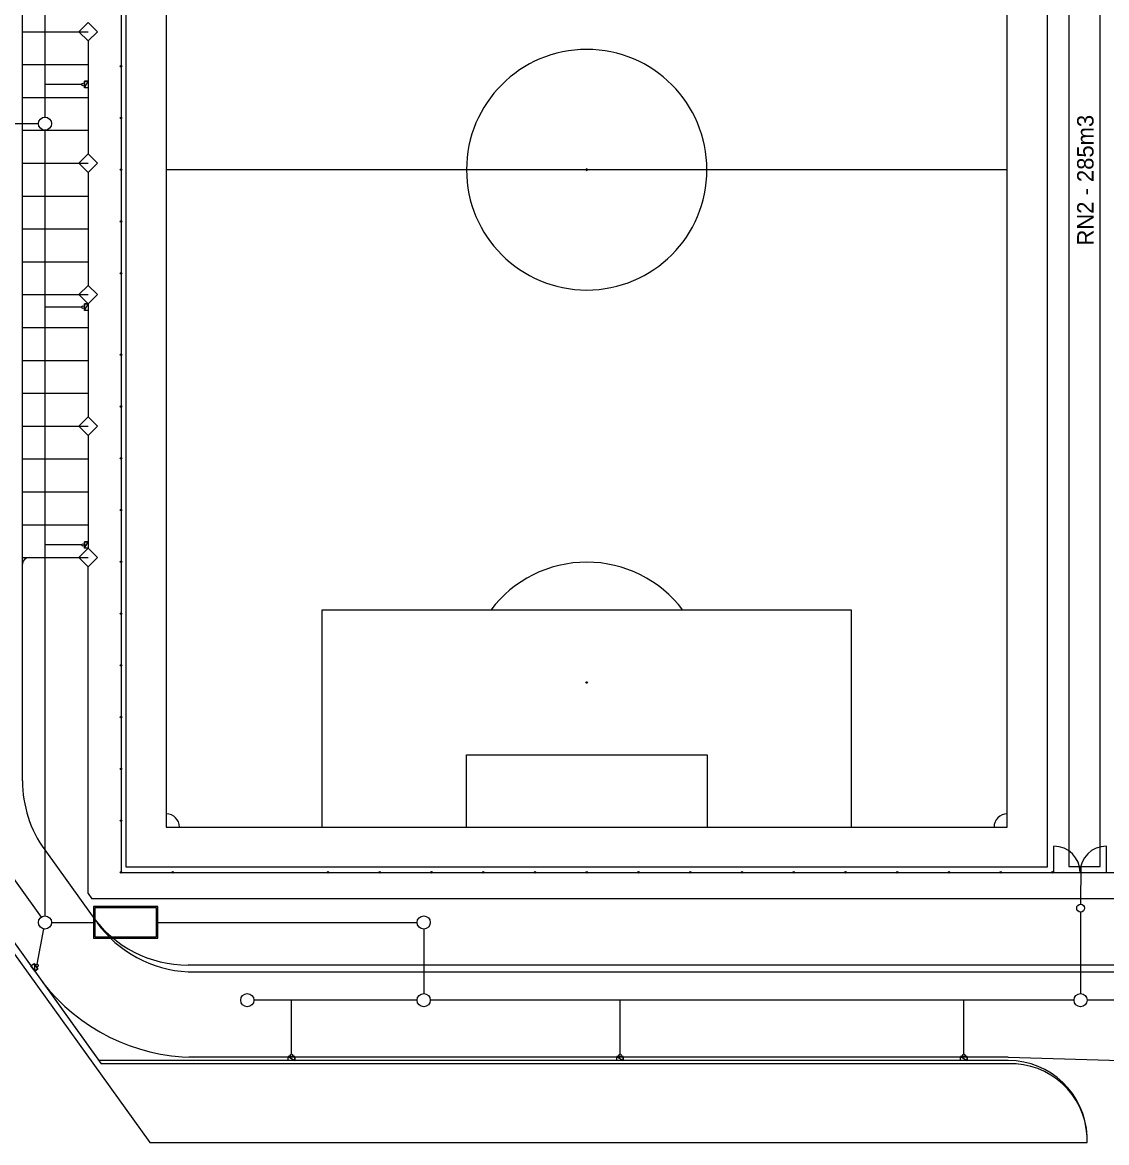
# Model space of a CAD drawing. Extents: x -264205 to -263659, y -1242401 to -1242060.
# Drawn here: x -264125.6 to -264043, y -1242315 to -1242229.8 of the extents above; entities that cross this region are included whole.
import ezdxf

# ---------------------------------------------------------------- set-up
doc = ezdxf.new("R2010")
doc.units = 0
for name, color, linetype in [('OBRUBNIKY_KOMUNIKACIE_PROJEKT', 7, 'Continuous'), ('SITUACIA_DSP_2D', 7, 'Continuous'), ('TDZ_VODOROVNE_PROJEKT', 7, 'Continuous')]:
    doc.layers.add(name, color=color, linetype=linetype)

msp = doc.modelspace()

# ---------------------------------------------------------------- linework, layer by layer
at = {"layer": 'OBRUBNIKY_KOMUNIKACIE_PROJEKT'}
for p, q in [((-264117.668, -1242294.032), (-264117.668, -1242187.932)), ((-264047.568, -1242187.932), (-264047.568, -1242294.032)), ((-264204.694, -1242191.482), (-264115.871, -1242314.982)), ((-264204.078, -1242191.482), (-264119.571, -1242308.982)), ((-264125.568, -1242270.982), (-264125.568, -1242191.482)), ((-264121.275, -1242230.482), (-264120.568, -1242229.775)), ((-264120.568, -1242229.775), (-264119.861, -1242230.482)), ((-264120.568, -1242231.189), (-264121.275, -1242230.482)), ((-264119.861, -1242230.482), (-264120.568, -1242231.189)), ((-264120.568, -1242231.189), (-264120.568, -1242239.774)), ((-264121.275, -1242240.482), (-264120.568, -1242239.775)), ((-264120.568, -1242239.775), (-264119.861, -1242240.482)), ((-264120.568, -1242241.189), (-264121.275, -1242240.482)), ((-264119.861, -1242240.482), (-264120.568, -1242241.189)), ((-264120.568, -1242241.189), (-264120.568, -1242249.774)), ((-264121.275, -1242250.482), (-264120.568, -1242249.775)), ((-264120.568, -1242249.775), (-264119.861, -1242250.482)), ((-264120.568, -1242251.189), (-264121.275, -1242250.482)), ((-264119.861, -1242250.482), (-264120.568, -1242251.189)), ((-264120.568, -1242251.191), (-264120.568, -1242259.775)), ((-264121.275, -1242260.482), (-264120.568, -1242259.775)), ((-264120.568, -1242261.189), (-264121.275, -1242260.482)), ((-264120.568, -1242259.775), (-264119.861, -1242260.482)), ((-264119.861, -1242260.482), (-264120.568, -1242261.189)), ((-264120.568, -1242261.189), (-264120.568, -1242269.774)), ((-264121.275, -1242270.482), (-264120.568, -1242269.775)), ((-264120.568, -1242269.775), (-264119.861, -1242270.482)), ((-264125.068, -1242270.482), (-264121.275, -1242270.482)), ((-264120.568, -1242271.189), (-264121.275, -1242270.482)), ((-264119.861, -1242270.482), (-264120.568, -1242271.189)), ((-264125.568, -1242287.467), (-264125.568, -1242270.982)), ((-264120.568, -1242296.035), (-264120.568, -1242271.189)), ((-264123.874, -1242292.722), (-264120.268, -1242297.737)), ((-264047.568, -1242294.032), (-264117.668, -1242294.032)), ((-264120.568, -1242296.035), (-264120.282, -1242296.432)), ((-264120.018, -1242296.432), (-264120.282, -1242296.432)), ((-263965.143, -1242296.432), (-264120.018, -1242296.432)), ((-263971.068, -1242301.482), (-264112.961, -1242301.482)), ((-264050.531, -1242308.982), (-264119.571, -1242308.982)), ((-264115.886, -1242314.982), (-264044.531, -1242314.982)), ((-264044.531, -1242314.982), (-264044.531, -1242314.482))]:
    msp.add_line(p, q, dxfattribs=at)
for centre, radius, start, end in [((-264125.068, -1242270.982), 0.5, 90, 180), ((-264116.568, -1242287.467), 9, 180, 215.72401), ((-264112.961, -1242292.482), 9, 215.72401, 270), ((-264050.347, -1242314.804), 5.825, 3.17009, 91.80902)]:
    msp.add_arc(centre, radius, start, end, dxfattribs=at)
at = {"layer": 'SITUACIA_DSP_2D'}
for p, q in [((-264118.068, -1242187.532), (-264118.068, -1242294.432)), ((-264117.668, -1242294.032), (-264117.668, -1242187.932)), ((-264047.568, -1242187.932), (-264047.568, -1242294.032)), ((-264204.694, -1242191.482), (-264115.871, -1242314.982)), ((-264204.078, -1242191.482), (-264119.75, -1242308.732)), ((-264114.618, -1242190.982), (-264114.618, -1242290.982)), ((-264050.618, -1242290.982), (-264050.618, -1242190.982)), ((-264045.927, -1242194.982), (-264045.927, -1242293.982)), ((-264043.527, -1242293.982), (-264043.527, -1242194.982)), ((-264123.854, -1242207), (-264123.854, -1242236.976)), ((-264121.275, -1242230.482), (-264120.568, -1242229.775)), ((-264120.568, -1242229.775), (-264119.861, -1242230.482)), ((-264120.568, -1242231.189), (-264121.275, -1242230.482)), ((-264119.861, -1242230.482), (-264120.568, -1242231.189)), ((-264120.568, -1242231.189), (-264120.568, -1242239.774)), ((-264118.008, -1242233.107), (-264118.128, -1242233.107)), ((-264118.068, -1242233.047), (-264118.068, -1242233.167)), ((-264121.058, -1242234.499), (-264123.854, -1242234.499)), ((-264120.858, -1242234.749), (-264120.858, -1242234.249)), ((-264120.858, -1242234.249), (-264120.568, -1242234.249)), ((-264120.858, -1242234.749), (-264120.568, -1242234.249)), ((-264120.858, -1242234.749), (-264120.568, -1242234.249)), ((-264120.568, -1242234.249), (-264120.858, -1242234.249)), ((-264120.858, -1242234.249), (-264120.858, -1242234.749)), ((-264120.568, -1242234.749), (-264120.858, -1242234.749)), ((-264120.568, -1242234.249), (-264120.568, -1242234.749)), ((-264154.318, -1242237.476), (-264124.354, -1242237.476)), ((-264118.008, -1242237.045), (-264118.128, -1242237.045)), ((-264118.068, -1242236.985), (-264118.068, -1242237.105)), ((-264123.854, -1242237.976), (-264123.854, -1242297.736)), ((-264121.275, -1242240.482), (-264120.568, -1242239.775)), ((-264120.568, -1242239.775), (-264119.861, -1242240.482)), ((-264120.568, -1242241.189), (-264121.275, -1242240.482)), ((-264119.861, -1242240.482), (-264120.568, -1242241.189)), ((-264118.008, -1242240.982), (-264118.128, -1242240.982)), ((-264118.068, -1242241.042), (-264118.068, -1242240.922)), ((-264050.618, -1242240.982), (-264114.618, -1242240.982)), ((-264120.568, -1242241.189), (-264120.568, -1242249.774)), ((-264118.008, -1242244.92), (-264118.128, -1242244.92)), ((-264118.068, -1242244.98), (-264118.068, -1242244.86)), ((-264118.008, -1242248.857), (-264118.128, -1242248.857)), ((-264118.068, -1242248.917), (-264118.068, -1242248.797)), ((-264121.275, -1242250.482), (-264120.568, -1242249.775)), ((-264120.568, -1242249.775), (-264119.861, -1242250.482)), ((-264120.568, -1242251.189), (-264121.275, -1242250.482)), ((-264120.857, -1242251.689), (-264120.857, -1242251.189)), ((-264120.857, -1242251.189), (-264120.567, -1242251.189)), ((-264120.857, -1242251.689), (-264120.567, -1242251.189)), ((-264120.857, -1242251.689), (-264120.567, -1242251.189)), ((-264120.567, -1242251.189), (-264120.857, -1242251.189)), ((-264120.857, -1242251.189), (-264120.857, -1242251.689)), ((-264119.861, -1242250.482), (-264120.568, -1242251.189)), ((-264120.568, -1242251.191), (-264120.568, -1242259.775)), ((-264120.567, -1242251.189), (-264120.567, -1242251.689)), ((-264121.057, -1242251.439), (-264123.853, -1242251.439)), ((-264120.567, -1242251.689), (-264120.857, -1242251.689)), ((-264118.008, -1242255.057), (-264118.128, -1242255.057)), ((-264118.068, -1242255.117), (-264118.068, -1242254.997)), ((-264152.757, -1242258.05), (-264124.146, -1242297.83)), ((-264152.757, -1242258.05), (-264124.146, -1242297.83)), ((-264118.008, -1242258.995), (-264118.128, -1242258.995)), ((-264118.068, -1242259.055), (-264118.068, -1242258.935)), ((-264121.275, -1242260.482), (-264120.568, -1242259.775)), ((-264120.568, -1242261.189), (-264121.275, -1242260.482)), ((-264120.568, -1242259.775), (-264119.861, -1242260.482)), ((-264119.861, -1242260.482), (-264120.568, -1242261.189)), ((-264120.568, -1242261.189), (-264120.568, -1242269.774)), ((-264118.008, -1242262.932), (-264118.128, -1242262.932)), ((-264118.068, -1242262.992), (-264118.068, -1242262.872)), ((-264118.008, -1242266.87), (-264118.128, -1242266.87)), ((-264118.068, -1242266.93), (-264118.068, -1242266.81)), ((-264121.058, -1242269.525), (-264123.854, -1242269.525)), ((-264121.275, -1242270.482), (-264120.568, -1242269.775)), ((-264120.857, -1242269.775), (-264120.857, -1242269.275)), ((-264120.857, -1242269.275), (-264120.567, -1242269.275)), ((-264120.857, -1242269.775), (-264120.567, -1242269.275)), ((-264120.857, -1242269.775), (-264120.567, -1242269.275)), ((-264120.567, -1242269.275), (-264120.857, -1242269.275)), ((-264120.857, -1242269.275), (-264120.857, -1242269.775)), ((-264120.567, -1242269.775), (-264120.857, -1242269.775)), ((-264120.568, -1242269.775), (-264119.861, -1242270.482)), ((-264120.567, -1242269.275), (-264120.567, -1242269.775)), ((-264125.068, -1242270.482), (-264121.275, -1242270.482)), ((-264120.568, -1242271.189), (-264121.275, -1242270.482)), ((-264119.861, -1242270.482), (-264120.568, -1242271.189)), ((-264118.008, -1242270.807), (-264118.128, -1242270.807)), ((-264118.068, -1242270.867), (-264118.068, -1242270.747)), ((-264125.568, -1242287.467), (-264125.568, -1242270.982)), ((-264120.568, -1242296.035), (-264120.568, -1242271.189)), ((-264120.568, -1242271.189), (-264120.568, -1242271.189)), ((-264118.008, -1242274.745), (-264118.128, -1242274.745)), ((-264118.068, -1242274.805), (-264118.068, -1242274.685)), ((-264062.458, -1242274.482), (-264102.778, -1242274.482)), ((-264102.778, -1242274.482), (-264102.778, -1242290.982)), ((-264062.458, -1242290.982), (-264062.458, -1242274.482)), ((-264118.008, -1242278.682), (-264118.128, -1242278.682)), ((-264118.068, -1242278.742), (-264118.068, -1242278.622)), ((-264118.008, -1242282.62), (-264118.128, -1242282.62)), ((-264118.068, -1242282.68), (-264118.068, -1242282.56)), ((-264091.778, -1242290.982), (-264091.778, -1242285.482)), ((-264091.778, -1242285.482), (-264073.458, -1242285.482)), ((-264073.458, -1242285.482), (-264073.458, -1242290.982)), ((-264118.008, -1242286.557), (-264118.128, -1242286.557)), ((-264118.068, -1242286.617), (-264118.068, -1242286.497)), ((-264118.068, -1242290.555), (-264118.068, -1242290.435)), ((-264118.008, -1242290.495), (-264118.128, -1242290.495)), ((-264114.618, -1242290.982), (-264050.618, -1242290.982)), ((-264123.874, -1242292.722), (-264120.268, -1242297.737)), ((-264047.068, -1242294.432), (-264047.068, -1242292.432)), ((-264043.068, -1242294.432), (-264043.068, -1242292.432)), ((-264118.008, -1242294.432), (-264118.128, -1242294.432)), ((-264118.068, -1242294.492), (-264118.068, -1242294.372)), ((-264118.068, -1242294.432), (-264045.118, -1242294.432)), ((-264047.568, -1242294.032), (-264117.668, -1242294.032)), ((-264114.069, -1242294.432), (-264114.189, -1242294.432)), ((-264114.129, -1242294.492), (-264114.129, -1242294.372)), ((-264102.252, -1242294.432), (-264102.372, -1242294.432)), ((-264102.312, -1242294.492), (-264102.312, -1242294.372)), ((-264098.313, -1242294.432), (-264098.433, -1242294.432)), ((-264098.373, -1242294.492), (-264098.373, -1242294.372)), ((-264094.374, -1242294.432), (-264094.494, -1242294.432)), ((-264094.434, -1242294.492), (-264094.434, -1242294.372)), ((-264090.436, -1242294.432), (-264090.556, -1242294.432)), ((-264090.496, -1242294.492), (-264090.496, -1242294.372)), ((-264086.497, -1242294.432), (-264086.617, -1242294.432)), ((-264086.557, -1242294.492), (-264086.557, -1242294.372)), ((-264082.558, -1242294.432), (-264082.678, -1242294.432)), ((-264082.618, -1242294.492), (-264082.618, -1242294.372)), ((-264078.619, -1242294.432), (-264078.739, -1242294.432)), ((-264078.679, -1242294.492), (-264078.679, -1242294.372)), ((-264074.68, -1242294.432), (-264074.8, -1242294.432)), ((-264074.74, -1242294.492), (-264074.74, -1242294.372)), ((-264070.741, -1242294.432), (-264070.861, -1242294.432)), ((-264070.801, -1242294.492), (-264070.801, -1242294.372)), ((-264066.802, -1242294.432), (-264066.922, -1242294.432)), ((-264066.862, -1242294.492), (-264066.862, -1242294.372)), ((-264062.863, -1242294.432), (-264062.983, -1242294.432)), ((-264062.923, -1242294.492), (-264062.923, -1242294.372)), ((-264058.924, -1242294.432), (-264059.044, -1242294.432)), ((-264058.984, -1242294.492), (-264058.984, -1242294.372)), ((-264054.986, -1242294.432), (-264055.106, -1242294.432)), ((-264055.046, -1242294.492), (-264055.046, -1242294.372)), ((-264051.047, -1242294.432), (-264051.167, -1242294.432)), ((-264051.107, -1242294.492), (-264051.107, -1242294.372)), ((-264047.108, -1242294.432), (-264047.228, -1242294.432)), ((-264047.168, -1242294.492), (-264047.168, -1242294.372)), ((-264045.927, -1242293.982), (-264043.527, -1242293.982)), ((-264045.568, -1242294.432), (-264044.568, -1242294.432)), ((-264045.118, -1242294.432), (-263972.068, -1242294.432)), ((-264045.017, -1242293.982), (-264045.027, -1242296.847)), ((-264120.568, -1242296.035), (-264120.282, -1242296.432)), ((-264120.018, -1242296.432), (-264120.282, -1242296.432)), ((-264120.154, -1242297.036), (-264120.154, -1242299.436)), ((-264115.254, -1242297.036), (-264120.154, -1242297.036)), ((-264115.354, -1242297.136), (-264120.054, -1242297.136)), ((-264120.054, -1242297.136), (-264120.054, -1242299.336)), ((-263965.143, -1242296.432), (-264120.018, -1242296.432)), ((-264115.354, -1242299.336), (-264115.354, -1242297.136)), ((-264115.254, -1242299.436), (-264115.254, -1242297.036)), ((-264045.027, -1242297.447), (-264045.027, -1242303.647)), ((-264124.444, -1242301.414), (-264123.946, -1242298.728)), ((-264123.354, -1242298.236), (-264120.154, -1242298.236)), ((-264115.254, -1242298.236), (-264095.527, -1242298.236)), ((-264095.027, -1242298.736), (-264095.027, -1242303.647)), ((-264120.154, -1242299.436), (-264115.254, -1242299.436)), ((-264120.054, -1242299.336), (-264115.354, -1242299.336)), ((-264124.925, -1242301.537), (-264124.69, -1242301.368)), ((-264124.69, -1242301.368), (-264124.398, -1242301.774)), ((-264124.69, -1242301.368), (-264124.633, -1242301.943)), ((-264124.69, -1242301.368), (-264124.633, -1242301.943)), ((-264124.398, -1242301.774), (-264124.69, -1242301.368)), ((-263971.068, -1242301.482), (-264112.961, -1242301.482)), ((-264124.633, -1242301.943), (-264124.925, -1242301.537)), ((-264124.398, -1242301.774), (-264124.633, -1242301.943)), ((-264124.633, -1242301.943), (-264124.398, -1242301.774)), ((-264095.527, -1242304.147), (-264107.955, -1242304.147)), ((-264105.085, -1242308.242), (-264105.085, -1242304.147)), ((-264045.527, -1242304.147), (-264094.527, -1242304.147)), ((-264080.085, -1242308.242), (-264080.085, -1242304.147)), ((-264053.913, -1242308.242), (-264053.913, -1242304.147)), ((-264004.396, -1242304.147), (-264044.527, -1242304.147)), ((-264050.531, -1242308.732), (-264119.75, -1242308.732)), ((-264105.335, -1242308.442), (-264104.835, -1242308.442)), ((-264105.335, -1242308.732), (-264105.335, -1242308.442)), ((-264105.335, -1242308.442), (-264104.835, -1242308.732)), ((-264105.335, -1242308.442), (-264104.835, -1242308.732)), ((-264104.835, -1242308.442), (-264105.335, -1242308.442)), ((-264104.835, -1242308.732), (-264105.335, -1242308.732)), ((-264104.835, -1242308.442), (-264104.835, -1242308.732)), ((-264104.835, -1242308.732), (-264104.835, -1242308.442)), ((-264080.335, -1242308.442), (-264079.835, -1242308.442)), ((-264080.335, -1242308.732), (-264080.335, -1242308.442)), ((-264080.335, -1242308.442), (-264079.835, -1242308.732)), ((-264080.335, -1242308.442), (-264079.835, -1242308.732)), ((-264079.835, -1242308.442), (-264080.335, -1242308.442)), ((-264079.835, -1242308.732), (-264080.335, -1242308.732)), ((-264079.835, -1242308.442), (-264079.835, -1242308.732)), ((-264079.835, -1242308.732), (-264079.835, -1242308.442)), ((-264054.163, -1242308.442), (-264053.663, -1242308.442)), ((-264054.163, -1242308.732), (-264054.163, -1242308.442)), ((-264054.163, -1242308.442), (-264053.663, -1242308.732)), ((-264054.163, -1242308.442), (-264053.663, -1242308.732)), ((-264053.663, -1242308.442), (-264054.163, -1242308.442)), ((-264053.663, -1242308.732), (-264054.163, -1242308.732)), ((-264053.663, -1242308.442), (-264053.663, -1242308.732)), ((-264053.663, -1242308.732), (-264053.663, -1242308.442)), ((-264115.886, -1242314.982), (-264044.531, -1242314.982)), ((-264044.531, -1242314.982), (-264044.531, -1242314.482))]:
    msp.add_line(p, q, dxfattribs=at)
for centre, radius in [((-264118.068, -1242233.107), 0.06), ((-264120.958, -1242234.499), 0.1), ((-264123.854, -1242237.476), 0.5), ((-264118.068, -1242237.045), 0.06), ((-264118.068, -1242240.982), 0.06), ((-264118.068, -1242244.92), 0.06), ((-264118.068, -1242248.857), 0.06), ((-264120.957, -1242251.439), 0.1), ((-264118.068, -1242255.057), 0.06), ((-264118.068, -1242258.995), 0.06), ((-264118.068, -1242262.932), 0.06), ((-264118.068, -1242266.87), 0.06), ((-264120.958, -1242269.525), 0.1), ((-264118.068, -1242270.807), 0.06), ((-264118.068, -1242274.745), 0.06), ((-264118.068, -1242278.682), 0.06), ((-264082.618, -1242279.982), 0.06), ((-264118.068, -1242282.62), 0.06), ((-264118.068, -1242286.557), 0.06), ((-264118.068, -1242290.495), 0.06), ((-264118.068, -1242294.432), 0.06), ((-264114.129, -1242294.432), 0.06), ((-264102.312, -1242294.432), 0.06), ((-264098.373, -1242294.432), 0.06), ((-264094.434, -1242294.432), 0.06), ((-264090.496, -1242294.432), 0.06), ((-264086.557, -1242294.432), 0.06), ((-264082.618, -1242294.432), 0.06), ((-264078.679, -1242294.432), 0.06), ((-264074.74, -1242294.432), 0.06), ((-264070.801, -1242294.432), 0.06), ((-264066.862, -1242294.432), 0.06), ((-264062.923, -1242294.432), 0.06), ((-264058.984, -1242294.432), 0.06), ((-264055.046, -1242294.432), 0.06), ((-264051.107, -1242294.432), 0.06), ((-264047.168, -1242294.432), 0.06), ((-264045.027, -1242297.147), 0.3), ((-264123.854, -1242298.236), 0.5), ((-264095.027, -1242298.236), 0.5), ((-264124.462, -1242301.513), 0.1), ((-264108.455, -1242304.147), 0.5), ((-264095.027, -1242304.147), 0.5), ((-264045.027, -1242304.147), 0.5), ((-264105.085, -1242308.342), 0.1), ((-264080.085, -1242308.342), 0.1), ((-264053.913, -1242308.342), 0.1)]:
    msp.add_circle(centre, radius, dxfattribs=at)
for centre, radius, start, end in [((-264082.618, -1242240.982), 9.15, 360, 180), ((-264082.618, -1242240.982), 9.15, 180, 360), ((-264082.618, -1242240.982), 0.0605, 90, 270), ((-264082.618, -1242240.982), 0.0605, 270, 90), ((-264125.068, -1242270.982), 0.5, 90, 180), ((-264082.618, -1242279.982), 9.15, 36.94821, 143.05179), ((-264082.618, -1242279.982), 0.0303, 90, 270), ((-264082.618, -1242279.982), 0.0303, 270, 90), ((-264116.568, -1242287.467), 9, 180, 215.72401), ((-264114.618, -1242290.982), 1, 0, 90), ((-264050.618, -1242290.982), 1, 90, 180), ((-264047.068, -1242294.432), 2, 0, 90), ((-264043.068, -1242294.432), 2, 90, 180), ((-264112.961, -1242292.482), 9, 215.72401, 270), ((-264050.561, -1242314.769), 6.037, 2.72538, 89.71237)]:
    msp.add_arc(centre, radius, start, end, dxfattribs=at)
at = {"layer": 'TDZ_VODOROVNE_PROJEKT'}
for p, q in [((-264125.568, -1242230.482), (-264120.568, -1242230.482)), ((-264125.568, -1242232.982), (-264120.568, -1242232.982)), ((-264125.568, -1242232.982), (-264120.568, -1242232.982)), ((-264125.568, -1242235.482), (-264120.568, -1242235.482)), ((-264125.568, -1242237.982), (-264120.568, -1242237.982)), ((-264125.568, -1242240.482), (-264120.568, -1242240.482)), ((-264125.568, -1242242.982), (-264120.568, -1242242.982)), ((-264125.568, -1242245.482), (-264120.568, -1242245.482)), ((-264125.568, -1242247.982), (-264120.568, -1242247.982)), ((-264125.568, -1242250.482), (-264120.568, -1242250.482)), ((-264125.568, -1242252.982), (-264120.568, -1242252.982)), ((-264125.568, -1242255.482), (-264120.568, -1242255.482)), ((-264125.568, -1242257.982), (-264120.568, -1242257.982)), ((-264125.568, -1242260.482), (-264120.568, -1242260.482)), ((-264125.568, -1242262.982), (-264120.568, -1242262.982)), ((-264125.568, -1242265.482), (-264120.568, -1242265.482)), ((-264125.568, -1242267.982), (-264120.568, -1242267.982)), ((-264125.568, -1242270.482), (-264120.568, -1242270.482)), ((-264112.961, -1242301.982), (-263971.806, -1242301.982)), ((-264050.531, -1242308.482), (-264112.906, -1242308.482)), ((-264050.531, -1242308.482), (-264032.141, -1242309.015))]:
    msp.add_line(p, q, dxfattribs=at)
for centre, radius, start, end in [((-264112.56, -1242292.924), 9.068, 215.87399, 267.4682), ((-264112.435, -1242293.84), 14.642, 217.62012, 269.49568)]:
    msp.add_arc(centre, radius, start, end, dxfattribs=at)

# ---------------------------------------------------------------- texts
at = {"layer": 'SITUACIA_DSP_2D'}
msp.add_text('RN2 - 285m3', height=1.25, rotation=90, dxfattribs=at).set_placement((-264044.042, -1242246.747))

doc.saveas('drawing.dxf')
